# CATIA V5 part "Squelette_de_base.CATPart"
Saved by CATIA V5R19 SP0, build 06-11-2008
Part number: Squelette_de_base
Publications: "Plan xy", "Plan yz", "Plan zx", "Point.1", "Point.2", "Point.3", "Point.4", "Point.5", "Point.6", "Droite.1"
Bounding box of the stored display mesh (mm): x 0 to 0, y -2391.774 to 2865.426, z -1458.497 to 2248.181
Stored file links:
  C:\Users\Guillaume et Fanny\Documents\IFMA\2A\IAO\Squelette_de_base.CATPart
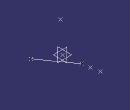
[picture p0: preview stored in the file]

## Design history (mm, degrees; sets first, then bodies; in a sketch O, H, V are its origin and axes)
Body1 (main body)
  Point1: (0, 0, 0)
  Point2: (0, 1443.75, 134.485)
  Point3: (0, 2865.426, 329.578)
  Point4: (0, 2099.603, 224.486)
  Point5: (0, -158.201, 2248.181)
  Point6: (0, -2391.774, -1458.497)
  Line1: type PtPt, SecondPoint Point6, FirstPoint Point2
